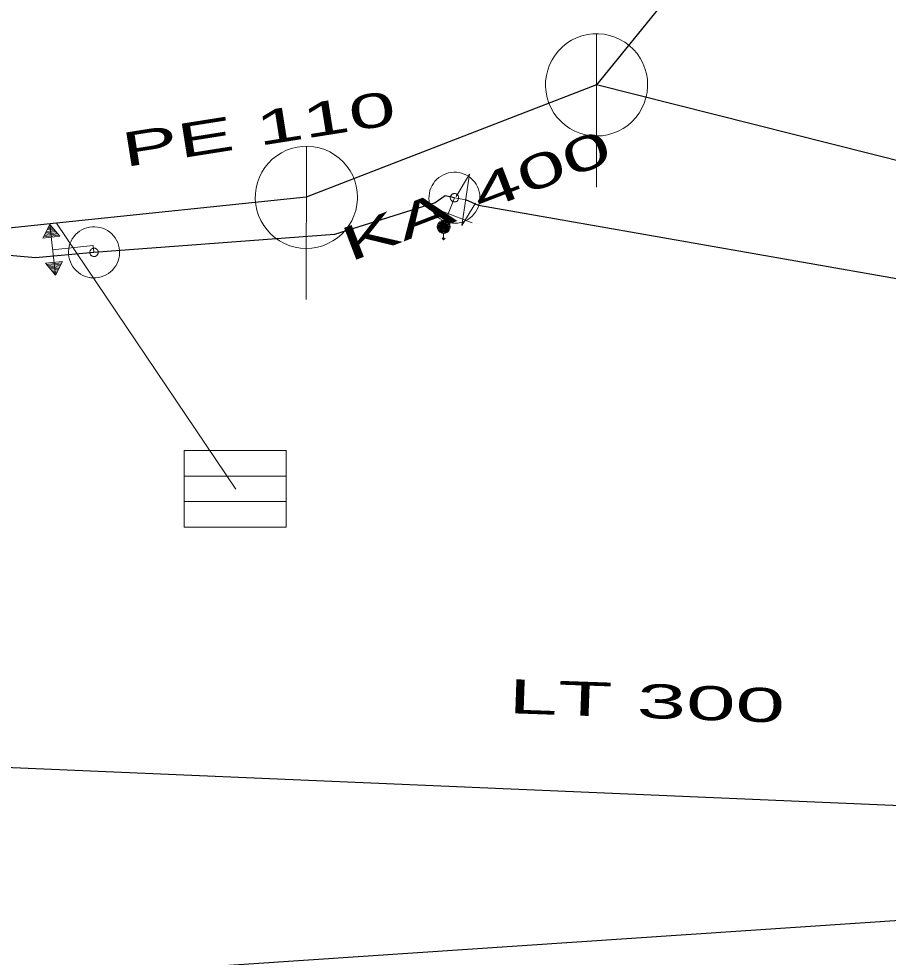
# Model space of a CAD drawing. Extents: x -687593 to -687108, y -975254 to -974717.
# Drawn here: x -687489.87 to -687472.85, y -974906.1 to -974887.74 of the extents above; entities that cross this region are included whole.
import ezdxf
from ezdxf.enums import TextEntityAlignment as Align

# ---------------------------------------------------------------- set-up
doc = ezdxf.new("R2010")
doc.units = 0
doc.header["$LTSCALE"] = 0.27
for name, color, linetype, lineweight in [('1', 7, 'Continuous', 25), ('11', 7, 'Continuous', 13), ('14', 7, 'Continuous', 13), ('17', 7, 'Continuous', 25), ('22', 7, 'Continuous', 13), ('34', 7, 'Continuous', 13), ('47', 7, 'Continuous', 13), ('9', 7, 'Continuous', 13)]:
    doc.layers.add(name, color=color, linetype=linetype, lineweight=lineweight)

msp = doc.modelspace()

# ---------------------------------------------------------------- linework, layer by layer
at = {"layer": '1'}
msp.add_lwpolyline([(-687190.553, -975166.941), (-687164.86, -975177.861), (-687155.924, -975158.837), (-687125.348, -975155.541), (-687124.826, -975139.621), (-687173.065, -975131.89), (-687231.828, -975028.025), (-687222.959, -975015.464), (-687237.898, -975004.026), (-687247.4, -975009.654), (-687276.892, -974983.781), (-687453.606, -974886.044), (-687460.232, -974860.45), (-687474.874, -974858.564), (-687482.889, -974882.272), (-687502.421, -974882.802), (-687499.452, -974907.164), (-687464.42, -974904.824), (-687331.319, -974973.728), (-687252.566, -975037.916), (-687192.379, -975151.48)], close=True, dxfattribs=at)
at = {"layer": '11'}
msp.add_line((-687485.62, -974896.94), (-687489.129, -974891.737), dxfattribs=at)
at = {"layer": '14', "lineweight": 25}
for p, q in [((-687462.829, -974869.623), (-687478.559, -974889.03)), ((-687478.559, -974889.03), (-687484.239, -974891.23)), ((-687459.21, -974893.91), (-687478.559, -974889.03))]:
    msp.add_line(p, q, dxfattribs=at)
at = {"layer": '14'}
for p, q in [((-687481.34, -974891.239), (-687481.46, -974891.55)), ((-687481.12, -974891.28), (-687481.34, -974891.239)), ((-687481.46, -974891.55), (-687481.55, -974891.809)), ((-687488.395, -974892.307), (-687488.41, -974892.17))]:
    msp.add_line(p, q, dxfattribs=at)
at = {"layer": '14', "lineweight": 25}
msp.add_lwpolyline([(-687484.239, -974891.23), (-687489.129, -974891.737), (-687501.93, -974893.079)], dxfattribs=at)
at = {"layer": '17'}
for points in [[(-687481.34, -974891.239), (-687481.52, -974891.199), (-687481.719, -974891.34), (-687483.69, -974891.96), (-687488.395, -974892.307)], [(-687440.137, -974904.525), (-687461.23, -974894.833), (-687480.87, -974891.39), (-687481.12, -974891.28)], [(-687488.395, -974892.307), (-687489.541, -974892.416), (-687490.936, -974892.292), (-687501.809, -974893.949), (-687502.346, -974893.334), (-687503.5, -974891.899)], [(-687397.965, -974929.018), (-687440.137, -974904.525), (-687515.147, -974901.318)]]:
    msp.add_lwpolyline(points, dxfattribs=at)
at = {"layer": '22'}
for p, q in [((-687478.559, -974891.03), (-687478.558, -974888.03)), ((-687484.239, -974893.23), (-687484.238, -974890.23)), ((-687486.631, -974896.683), (-687484.631, -974896.683)), ((-687486.631, -974897.183), (-687484.631, -974897.183))]:
    msp.add_line(p, q, dxfattribs=at)
for points in [[(-687477.559, -974889.03), (-687477.564, -974888.921), (-687477.582, -974888.813), (-687477.612, -974888.707), (-687477.652, -974888.606), (-687477.704, -974888.509), (-687477.766, -974888.419), (-687477.838, -974888.336), (-687477.918, -974888.262), (-687478.006, -974888.196), (-687478.1, -974888.141), (-687478.2, -974888.096), (-687478.305, -974888.063), (-687478.412, -974888.041), (-687478.521, -974888.031), (-687478.631, -974888.033), (-687478.739, -974888.047), (-687478.846, -974888.072), (-687478.949, -974888.109), (-687479.047, -974888.158), (-687479.139, -974888.216), (-687479.225, -974888.285), (-687479.302, -974888.362), (-687479.371, -974888.448), (-687479.43, -974888.54), (-687479.478, -974888.638), (-687479.515, -974888.741), (-687479.541, -974888.848), (-687479.555, -974888.956), (-687479.558, -974889.066), (-687479.548, -974889.175), (-687479.527, -974889.282), (-687479.493, -974889.386), (-687479.449, -974889.486), (-687479.394, -974889.581), (-687479.328, -974889.669), (-687479.254, -974889.749), (-687479.171, -974889.821), (-687479.081, -974889.883), (-687478.985, -974889.935), (-687478.883, -974889.976), (-687478.778, -974890.006), (-687478.67, -974890.024), (-687478.56, -974890.03), (-687478.451, -974890.024), (-687478.343, -974890.006), (-687478.238, -974889.977), (-687478.136, -974889.936), (-687478.039, -974889.884), (-687477.949, -974889.822), (-687477.866, -974889.751), (-687477.791, -974889.671), (-687477.726, -974889.583), (-687477.67, -974889.489), (-687477.626, -974889.389), (-687477.592, -974889.285), (-687477.57, -974889.177), (-687477.56, -974889.068)], [(-687483.239, -974891.23), (-687483.244, -974891.121), (-687483.262, -974891.013), (-687483.292, -974890.907), (-687483.332, -974890.806), (-687483.384, -974890.709), (-687483.446, -974890.619), (-687483.518, -974890.536), (-687483.598, -974890.462), (-687483.686, -974890.396), (-687483.78, -974890.341), (-687483.88, -974890.296), (-687483.985, -974890.263), (-687484.092, -974890.241), (-687484.201, -974890.231), (-687484.311, -974890.233), (-687484.419, -974890.247), (-687484.526, -974890.272), (-687484.629, -974890.309), (-687484.727, -974890.358), (-687484.819, -974890.416), (-687484.905, -974890.485), (-687484.982, -974890.562), (-687485.051, -974890.648), (-687485.11, -974890.74), (-687485.158, -974890.838), (-687485.195, -974890.941), (-687485.221, -974891.048), (-687485.235, -974891.156), (-687485.238, -974891.266), (-687485.228, -974891.375), (-687485.207, -974891.482), (-687485.173, -974891.586), (-687485.129, -974891.686), (-687485.074, -974891.781), (-687485.008, -974891.869), (-687484.934, -974891.949), (-687484.851, -974892.021), (-687484.761, -974892.083), (-687484.665, -974892.135), (-687484.563, -974892.176), (-687484.458, -974892.206), (-687484.35, -974892.224), (-687484.24, -974892.23), (-687484.131, -974892.224), (-687484.023, -974892.206), (-687483.918, -974892.177), (-687483.816, -974892.136), (-687483.719, -974892.084), (-687483.629, -974892.022), (-687483.546, -974891.951), (-687483.471, -974891.871), (-687483.406, -974891.783), (-687483.35, -974891.689), (-687483.306, -974891.589), (-687483.272, -974891.485), (-687483.25, -974891.377), (-687483.24, -974891.268)], [(-687486.631, -974896.183), (-687484.631, -974896.183), (-687484.631, -974897.683), (-687486.631, -974897.683)]]:
    msp.add_lwpolyline(points, close=True, dxfattribs=at)
at = {"layer": '34'}
for p, q in [((-687480.993, -974891.73), (-687481.926, -974891.369)), ((-687489.369, -974891.976), (-687489.103, -974891.944)), ((-687489.352, -974891.95), (-687489.125, -974891.922)), ((-687489.339, -974891.923), (-687489.144, -974891.9)), ((-687489.326, -974891.899), (-687489.161, -974891.879)), ((-687489.314, -974891.869), (-687489.181, -974891.854)), ((-687489.301, -974891.845), (-687489.199, -974891.832)), ((-687489.284, -974891.819), (-687489.222, -974891.811)), ((-687489.273, -974891.788), (-687489.241, -974891.785)), ((-687489.381, -974892.004), (-687489.084, -974891.969)), ((-687489.205, -974892.257), (-687488.41, -974892.17)), ((-687489.011, -974892.487), (-687489.151, -974892.75)), ((-687489.322, -974892.541), (-687489.024, -974892.511)), ((-687489.304, -974892.566), (-687489.037, -974892.54)), ((-687489.282, -974892.588), (-687489.055, -974892.566)), ((-687489.264, -974892.611), (-687489.068, -974892.592)), ((-687489.246, -974892.632), (-687489.08, -974892.616)), ((-687489.228, -974892.658), (-687489.094, -974892.645)), ((-687489.209, -974892.68), (-687489.108, -974892.669)), ((-687489.188, -974892.701), (-687489.125, -974892.695)), ((-687489.17, -974892.729), (-687489.138, -974892.725))]:
    msp.add_line(p, q, dxfattribs=at)
for points in [[(-687489.259, -974891.764), (-687489.394, -974892.03), (-687489.065, -974891.99)], [(-687489.065, -974891.99), (-687489.259, -974891.764), (-687489.151, -974892.75)], [(-687489.151, -974892.75), (-687489.341, -974892.519), (-687489.011, -974892.487)]]:
    msp.add_lwpolyline(points, dxfattribs=at)
at = {"layer": '47'}
msp.add_line((-687481.193, -974891.784), (-687480.93, -974891.346), dxfattribs=at)
for points in [[(-687481.831, -974891.149), (-687481.838, -974891.201), (-687481.839, -974891.253), (-687481.834, -974891.305), (-687481.825, -974891.356), (-687481.81, -974891.407), (-687481.79, -974891.455), (-687481.764, -974891.501), (-687481.734, -974891.544), (-687481.701, -974891.583), (-687481.663, -974891.62), (-687481.621, -974891.652), (-687481.576, -974891.678), (-687481.529, -974891.701), (-687481.48, -974891.718), (-687481.429, -974891.73), (-687481.377, -974891.737), (-687481.325, -974891.738), (-687481.272, -974891.734), (-687481.222, -974891.724), (-687481.171, -974891.709), (-687481.123, -974891.689), (-687481.076, -974891.663), (-687481.033, -974891.634), (-687480.994, -974891.6), (-687480.958, -974891.562), (-687480.926, -974891.52), (-687480.899, -974891.475), (-687480.877, -974891.428), (-687480.86, -974891.379), (-687480.848, -974891.328), (-687480.841, -974891.276), (-687480.84, -974891.224), (-687480.843, -974891.171), (-687480.854, -974891.121), (-687480.869, -974891.07), (-687480.888, -974891.022), (-687480.914, -974890.975), (-687480.943, -974890.932), (-687480.978, -974890.893), (-687481.016, -974890.857), (-687481.058, -974890.825), (-687481.102, -974890.798), (-687481.15, -974890.776), (-687481.199, -974890.759), (-687481.25, -974890.747), (-687481.302, -974890.74), (-687481.354, -974890.739), (-687481.406, -974890.743), (-687481.457, -974890.753), (-687481.508, -974890.768), (-687481.556, -974890.787), (-687481.602, -974890.813), (-687481.645, -974890.843), (-687481.684, -974890.877), (-687481.721, -974890.915), (-687481.753, -974890.957), (-687481.779, -974891.001), (-687481.802, -974891.049), (-687481.819, -974891.098)], [(-687481.42, -974891.224), (-687481.422, -974891.233), (-687481.421, -974891.241), (-687481.421, -974891.249), (-687481.419, -974891.258), (-687481.417, -974891.266), (-687481.413, -974891.274), (-687481.409, -974891.282), (-687481.405, -974891.289), (-687481.399, -974891.295), (-687481.393, -974891.301), (-687481.385, -974891.306), (-687481.378, -974891.311), (-687481.371, -974891.314), (-687481.363, -974891.318), (-687481.354, -974891.319), (-687481.345, -974891.321), (-687481.337, -974891.32), (-687481.329, -974891.32), (-687481.32, -974891.318), (-687481.312, -974891.316), (-687481.304, -974891.312), (-687481.296, -974891.308), (-687481.289, -974891.304), (-687481.282, -974891.298), (-687481.277, -974891.292), (-687481.272, -974891.284), (-687481.267, -974891.277), (-687481.264, -974891.27), (-687481.26, -974891.262), (-687481.259, -974891.253), (-687481.257, -974891.244), (-687481.258, -974891.236), (-687481.258, -974891.228), (-687481.26, -974891.219), (-687481.262, -974891.211), (-687481.265, -974891.203), (-687481.27, -974891.195), (-687481.274, -974891.188), (-687481.28, -974891.181), (-687481.286, -974891.176), (-687481.294, -974891.171), (-687481.301, -974891.166), (-687481.308, -974891.163), (-687481.316, -974891.159), (-687481.325, -974891.158), (-687481.334, -974891.156), (-687481.342, -974891.157), (-687481.35, -974891.157), (-687481.359, -974891.159), (-687481.367, -974891.161), (-687481.375, -974891.164), (-687481.383, -974891.169), (-687481.39, -974891.173), (-687481.396, -974891.179), (-687481.402, -974891.185), (-687481.407, -974891.193), (-687481.412, -974891.2), (-687481.415, -974891.207), (-687481.419, -974891.215)], [(-687488.893, -974892.343), (-687488.886, -974892.395), (-687488.875, -974892.446), (-687488.857, -974892.495), (-687488.835, -974892.543), (-687488.808, -974892.588), (-687488.776, -974892.629), (-687488.74, -974892.667), (-687488.7, -974892.701), (-687488.658, -974892.731), (-687488.612, -974892.757), (-687488.563, -974892.777), (-687488.513, -974892.792), (-687488.462, -974892.802), (-687488.41, -974892.806), (-687488.358, -974892.805), (-687488.306, -974892.798), (-687488.255, -974892.787), (-687488.205, -974892.769), (-687488.158, -974892.747), (-687488.113, -974892.72), (-687488.072, -974892.688), (-687488.033, -974892.652), (-687487.999, -974892.612), (-687487.969, -974892.57), (-687487.944, -974892.524), (-687487.924, -974892.475), (-687487.908, -974892.425), (-687487.899, -974892.374), (-687487.895, -974892.322), (-687487.896, -974892.27), (-687487.903, -974892.218), (-687487.914, -974892.167), (-687487.931, -974892.117), (-687487.954, -974892.07), (-687487.981, -974892.025), (-687488.012, -974891.984), (-687488.048, -974891.945), (-687488.088, -974891.911), (-687488.131, -974891.881), (-687488.177, -974891.856), (-687488.226, -974891.836), (-687488.275, -974891.82), (-687488.327, -974891.811), (-687488.379, -974891.807), (-687488.431, -974891.808), (-687488.483, -974891.815), (-687488.534, -974891.826), (-687488.583, -974891.843), (-687488.631, -974891.866), (-687488.676, -974891.893), (-687488.717, -974891.924), (-687488.755, -974891.96), (-687488.789, -974892), (-687488.819, -974892.043), (-687488.845, -974892.089), (-687488.865, -974892.138), (-687488.88, -974892.187), (-687488.89, -974892.239), (-687488.894, -974892.291)], [(-687488.476, -974892.313), (-687488.476, -974892.322), (-687488.473, -974892.329), (-687488.47, -974892.337), (-687488.467, -974892.345), (-687488.462, -974892.353), (-687488.457, -974892.359), (-687488.451, -974892.366), (-687488.445, -974892.371), (-687488.438, -974892.376), (-687488.43, -974892.38), (-687488.422, -974892.384), (-687488.414, -974892.386), (-687488.406, -974892.388), (-687488.397, -974892.389), (-687488.388, -974892.388), (-687488.379, -974892.388), (-687488.372, -974892.385), (-687488.364, -974892.382), (-687488.356, -974892.379), (-687488.348, -974892.374), (-687488.342, -974892.369), (-687488.335, -974892.363), (-687488.33, -974892.357), (-687488.324, -974892.349), (-687488.321, -974892.342), (-687488.317, -974892.334), (-687488.315, -974892.326), (-687488.313, -974892.318), (-687488.312, -974892.309), (-687488.313, -974892.3), (-687488.313, -974892.291), (-687488.316, -974892.284), (-687488.319, -974892.276), (-687488.322, -974892.268), (-687488.327, -974892.26), (-687488.331, -974892.254), (-687488.338, -974892.247), (-687488.344, -974892.242), (-687488.352, -974892.236), (-687488.359, -974892.233), (-687488.367, -974892.229), (-687488.375, -974892.227), (-687488.383, -974892.225), (-687488.392, -974892.224), (-687488.401, -974892.225), (-687488.41, -974892.225), (-687488.417, -974892.228), (-687488.425, -974892.231), (-687488.433, -974892.234), (-687488.441, -974892.239), (-687488.447, -974892.243), (-687488.454, -974892.25), (-687488.459, -974892.256), (-687488.464, -974892.263), (-687488.468, -974892.271), (-687488.472, -974892.279), (-687488.474, -974892.287), (-687488.476, -974892.295), (-687488.477, -974892.304)]]:
    msp.add_lwpolyline(points, close=True, dxfattribs=at)
msp.add_lwpolyline([(-687481.193, -974891.784), (-687481.046, -974890.775), (-687481.309, -974891.213)], dxfattribs=at)
at = {"layer": '9'}
msp.add_line((-687481.551, -974891.936), (-687481.551, -974892.061), dxfattribs=at)
for points in [[(-687481.677, -974891.808), (-687481.676, -974891.821), (-687481.674, -974891.834), (-687481.671, -974891.847), (-687481.666, -974891.859), (-687481.66, -974891.871), (-687481.653, -974891.882), (-687481.645, -974891.892), (-687481.635, -974891.902), (-687481.625, -974891.91), (-687481.614, -974891.917), (-687481.602, -974891.923), (-687481.59, -974891.928), (-687481.577, -974891.931), (-687481.564, -974891.933), (-687481.551, -974891.936), (-687481.538, -974891.935), (-687481.525, -974891.933), (-687481.512, -974891.93), (-687481.5, -974891.925), (-687481.488, -974891.919), (-687481.477, -974891.912), (-687481.467, -974891.904), (-687481.457, -974891.894), (-687481.449, -974891.884), (-687481.442, -974891.873), (-687481.436, -974891.861), (-687481.431, -974891.849), (-687481.428, -974891.836), (-687481.426, -974891.823), (-687481.424, -974891.81), (-687481.425, -974891.797), (-687481.427, -974891.784), (-687481.43, -974891.771), (-687481.435, -974891.759), (-687481.441, -974891.747), (-687481.448, -974891.736), (-687481.456, -974891.726), (-687481.466, -974891.716), (-687481.476, -974891.708), (-687481.487, -974891.701), (-687481.499, -974891.695), (-687481.511, -974891.69), (-687481.524, -974891.687), (-687481.537, -974891.685), (-687481.55, -974891.683), (-687481.563, -974891.683), (-687481.576, -974891.685), (-687481.589, -974891.688), (-687481.601, -974891.693), (-687481.613, -974891.699), (-687481.624, -974891.706), (-687481.634, -974891.714), (-687481.644, -974891.724), (-687481.652, -974891.734), (-687481.659, -974891.745), (-687481.665, -974891.757), (-687481.67, -974891.769), (-687481.673, -974891.782), (-687481.675, -974891.795)], [(-687481.657, -974891.808), (-687481.657, -974891.819), (-687481.655, -974891.83), (-687481.652, -974891.841), (-687481.648, -974891.851), (-687481.643, -974891.861), (-687481.637, -974891.87), (-687481.63, -974891.879), (-687481.622, -974891.887), (-687481.613, -974891.894), (-687481.604, -974891.9), (-687481.594, -974891.905), (-687481.584, -974891.909), (-687481.573, -974891.912), (-687481.562, -974891.914), (-687481.551, -974891.914), (-687481.54, -974891.916), (-687481.529, -974891.914), (-687481.518, -974891.911), (-687481.508, -974891.907), (-687481.498, -974891.902), (-687481.489, -974891.896), (-687481.48, -974891.889), (-687481.472, -974891.881), (-687481.465, -974891.872), (-687481.459, -974891.863), (-687481.454, -974891.853), (-687481.45, -974891.843), (-687481.447, -974891.832), (-687481.445, -974891.821), (-687481.444, -974891.81), (-687481.444, -974891.799), (-687481.446, -974891.788), (-687481.449, -974891.777), (-687481.453, -974891.767), (-687481.458, -974891.757), (-687481.464, -974891.748), (-687481.471, -974891.739), (-687481.479, -974891.731), (-687481.488, -974891.724), (-687481.497, -974891.718), (-687481.507, -974891.713), (-687481.517, -974891.709), (-687481.528, -974891.706), (-687481.539, -974891.704), (-687481.55, -974891.703), (-687481.561, -974891.702), (-687481.572, -974891.704), (-687481.583, -974891.707), (-687481.593, -974891.711), (-687481.603, -974891.716), (-687481.612, -974891.722), (-687481.621, -974891.729), (-687481.629, -974891.737), (-687481.636, -974891.746), (-687481.642, -974891.755), (-687481.647, -974891.765), (-687481.651, -974891.775), (-687481.654, -974891.786), (-687481.656, -974891.797)], [(-687481.638, -974891.808), (-687481.637, -974891.817), (-687481.636, -974891.826), (-687481.633, -974891.835), (-687481.63, -974891.843), (-687481.626, -974891.851), (-687481.621, -974891.859), (-687481.615, -974891.866), (-687481.609, -974891.872), (-687481.602, -974891.878), (-687481.594, -974891.883), (-687481.586, -974891.887), (-687481.578, -974891.89), (-687481.569, -974891.893), (-687481.56, -974891.894), (-687481.551, -974891.897), (-687481.542, -974891.896), (-687481.533, -974891.895), (-687481.524, -974891.892), (-687481.516, -974891.889), (-687481.508, -974891.885), (-687481.5, -974891.88), (-687481.493, -974891.874), (-687481.487, -974891.868), (-687481.481, -974891.861), (-687481.476, -974891.853), (-687481.472, -974891.845), (-687481.469, -974891.837), (-687481.466, -974891.828), (-687481.465, -974891.819), (-687481.463, -974891.81), (-687481.464, -974891.801), (-687481.465, -974891.792), (-687481.468, -974891.783), (-687481.471, -974891.775), (-687481.475, -974891.767), (-687481.48, -974891.759), (-687481.486, -974891.752), (-687481.492, -974891.746), (-687481.499, -974891.74), (-687481.507, -974891.735), (-687481.515, -974891.731), (-687481.523, -974891.728), (-687481.532, -974891.725), (-687481.541, -974891.724), (-687481.55, -974891.722), (-687481.559, -974891.722), (-687481.568, -974891.723), (-687481.577, -974891.726), (-687481.585, -974891.729), (-687481.593, -974891.733), (-687481.601, -974891.738), (-687481.608, -974891.744), (-687481.614, -974891.75), (-687481.62, -974891.757), (-687481.625, -974891.765), (-687481.629, -974891.773), (-687481.632, -974891.781), (-687481.635, -974891.79), (-687481.636, -974891.799)], [(-687481.618, -974891.808), (-687481.618, -974891.815), (-687481.616, -974891.822), (-687481.615, -974891.829), (-687481.612, -974891.835), (-687481.609, -974891.841), (-687481.605, -974891.847), (-687481.601, -974891.853), (-687481.596, -974891.858), (-687481.59, -974891.862), (-687481.584, -974891.866), (-687481.578, -974891.869), (-687481.572, -974891.872), (-687481.565, -974891.873), (-687481.558, -974891.875), (-687481.551, -974891.875), (-687481.544, -974891.877), (-687481.537, -974891.875), (-687481.53, -974891.874), (-687481.524, -974891.871), (-687481.517, -974891.868), (-687481.512, -974891.864), (-687481.506, -974891.86), (-687481.501, -974891.855), (-687481.497, -974891.849), (-687481.493, -974891.843), (-687481.49, -974891.837), (-687481.487, -974891.831), (-687481.485, -974891.824), (-687481.484, -974891.817), (-687481.483, -974891.81), (-687481.483, -974891.803), (-687481.484, -974891.796), (-687481.486, -974891.789), (-687481.489, -974891.783), (-687481.492, -974891.776), (-687481.496, -974891.771), (-687481.5, -974891.765), (-687481.505, -974891.76), (-687481.511, -974891.756), (-687481.516, -974891.752), (-687481.523, -974891.749), (-687481.529, -974891.746), (-687481.536, -974891.744), (-687481.543, -974891.743), (-687481.55, -974891.742), (-687481.557, -974891.741), (-687481.564, -974891.742), (-687481.571, -974891.744), (-687481.577, -974891.747), (-687481.583, -974891.75), (-687481.589, -974891.754), (-687481.595, -974891.758), (-687481.6, -974891.763), (-687481.604, -974891.769), (-687481.608, -974891.774), (-687481.611, -974891.781), (-687481.614, -974891.787), (-687481.615, -974891.794), (-687481.617, -974891.801)], [(-687481.598, -974891.808), (-687481.598, -974891.813), (-687481.597, -974891.818), (-687481.596, -974891.823), (-687481.594, -974891.827), (-687481.592, -974891.832), (-687481.589, -974891.836), (-687481.586, -974891.839), (-687481.582, -974891.843), (-687481.579, -974891.846), (-687481.575, -974891.849), (-687481.57, -974891.851), (-687481.566, -974891.853), (-687481.561, -974891.854), (-687481.556, -974891.855), (-687481.551, -974891.855), (-687481.546, -974891.857), (-687481.541, -974891.856), (-687481.536, -974891.855), (-687481.532, -974891.853), (-687481.527, -974891.851), (-687481.523, -974891.848), (-687481.519, -974891.845), (-687481.516, -974891.841), (-687481.513, -974891.838), (-687481.51, -974891.834), (-687481.508, -974891.829), (-687481.506, -974891.825), (-687481.505, -974891.82), (-687481.504, -974891.815), (-687481.504, -974891.81), (-687481.503, -974891.805), (-687481.504, -974891.8), (-687481.505, -974891.795), (-687481.507, -974891.791), (-687481.509, -974891.786), (-687481.512, -974891.782), (-687481.515, -974891.778), (-687481.518, -974891.775), (-687481.522, -974891.772), (-687481.526, -974891.769), (-687481.531, -974891.767), (-687481.535, -974891.765), (-687481.54, -974891.764), (-687481.545, -974891.763), (-687481.55, -974891.762), (-687481.555, -974891.761), (-687481.56, -974891.762), (-687481.565, -974891.763), (-687481.569, -974891.765), (-687481.574, -974891.767), (-687481.578, -974891.77), (-687481.581, -974891.773), (-687481.585, -974891.776), (-687481.588, -974891.78), (-687481.591, -974891.784), (-687481.593, -974891.789), (-687481.595, -974891.793), (-687481.596, -974891.798), (-687481.597, -974891.803)], [(-687481.578, -974891.808), (-687481.578, -974891.811), (-687481.578, -974891.814), (-687481.577, -974891.816), (-687481.576, -974891.819), (-687481.575, -974891.822), (-687481.573, -974891.824), (-687481.571, -974891.826), (-687481.569, -974891.828), (-687481.567, -974891.83), (-687481.565, -974891.832), (-687481.562, -974891.833), (-687481.559, -974891.834), (-687481.557, -974891.835), (-687481.554, -974891.835), (-687481.551, -974891.835), (-687481.548, -974891.837), (-687481.545, -974891.837), (-687481.542, -974891.836), (-687481.54, -974891.835), (-687481.537, -974891.834), (-687481.535, -974891.832), (-687481.532, -974891.83), (-687481.53, -974891.828), (-687481.529, -974891.826), (-687481.527, -974891.824), (-687481.526, -974891.821), (-687481.525, -974891.818), (-687481.524, -974891.816), (-687481.524, -974891.813), (-687481.522, -974891.81), (-687481.523, -974891.807), (-687481.523, -974891.804), (-687481.524, -974891.801), (-687481.525, -974891.799), (-687481.526, -974891.796), (-687481.528, -974891.794), (-687481.529, -974891.791), (-687481.531, -974891.789), (-687481.534, -974891.788), (-687481.536, -974891.786), (-687481.539, -974891.785), (-687481.541, -974891.784), (-687481.544, -974891.783), (-687481.547, -974891.783), (-687481.55, -974891.781), (-687481.553, -974891.781), (-687481.556, -974891.781), (-687481.558, -974891.782), (-687481.561, -974891.783), (-687481.564, -974891.784), (-687481.566, -974891.786), (-687481.568, -974891.787), (-687481.57, -974891.789), (-687481.572, -974891.792), (-687481.574, -974891.794), (-687481.575, -974891.797), (-687481.576, -974891.799), (-687481.577, -974891.802), (-687481.577, -974891.805)], [(-687481.559, -974891.808), (-687481.559, -974891.809), (-687481.559, -974891.81), (-687481.558, -974891.81), (-687481.558, -974891.811), (-687481.558, -974891.812), (-687481.557, -974891.813), (-687481.557, -974891.813), (-687481.556, -974891.814), (-687481.556, -974891.814), (-687481.555, -974891.815), (-687481.554, -974891.815), (-687481.553, -974891.815), (-687481.553, -974891.816), (-687481.552, -974891.816), (-687481.551, -974891.816), (-687481.55, -974891.817), (-687481.549, -974891.817), (-687481.549, -974891.817), (-687481.548, -974891.817), (-687481.547, -974891.817), (-687481.546, -974891.816), (-687481.546, -974891.816), (-687481.545, -974891.815), (-687481.545, -974891.815), (-687481.544, -974891.814), (-687481.544, -974891.813), (-687481.543, -974891.812), (-687481.543, -974891.812), (-687481.543, -974891.811), (-687481.542, -974891.81), (-687481.542, -974891.809), (-687481.542, -974891.808), (-687481.542, -974891.808), (-687481.543, -974891.807), (-687481.543, -974891.806), (-687481.544, -974891.805), (-687481.544, -974891.805), (-687481.545, -974891.804), (-687481.545, -974891.804), (-687481.546, -974891.803), (-687481.547, -974891.803), (-687481.548, -974891.802), (-687481.548, -974891.802), (-687481.549, -974891.802), (-687481.55, -974891.801), (-687481.551, -974891.801), (-687481.552, -974891.8), (-687481.552, -974891.8), (-687481.553, -974891.801), (-687481.554, -974891.801), (-687481.555, -974891.802), (-687481.555, -974891.802), (-687481.556, -974891.803), (-687481.556, -974891.803), (-687481.557, -974891.804), (-687481.557, -974891.805), (-687481.557, -974891.806), (-687481.558, -974891.806), (-687481.558, -974891.807)]]:
    msp.add_lwpolyline(points, close=True, dxfattribs=at)
msp.add_lwpolyline([(-687481.52, -974892.027), (-687481.551, -974892.061), (-687481.582, -974892.025)], dxfattribs=at)

# ---------------------------------------------------------------- texts
at = {"layer": '1'}
for s, rotation, width, p in [('PE 110', 9, 1.85, (-687485.1201, -974890.217)), ('PE 110', 9, 1.85, (-687485.1201, -974890.217)), ('PE 110', 9, 1.85, (-687485.1201, -974890.217)), ('PE 110', 9, 1.85, (-687485.1201, -974890.217)), ('PE 110', 9, 1.85, (-687485.1201, -974890.217)), ('KA 400', 21, 1.9, (-687480.7965, -974891.5043)), ('KA 400', 21, 1.9, (-687480.7965, -974891.5043)), ('KA 400', 21, 1.9, (-687480.7965, -974891.5043)), ('KA 400', 21, 1.9, (-687480.7965, -974891.5043)), ('KA 400', 21, 1.9, (-687480.7965, -974891.5043)), ('LT 300', 358, 1.95, (-687477.5876, -974901.4153)), ('LT 300', 358, 1.95, (-687477.5876, -974901.4153)), ('LT 300', 358, 1.95, (-687477.5876, -974901.4153)), ('LT 300', 358, 1.95, (-687477.5876, -974901.4153)), ('LT 300', 358, 1.95, (-687477.5876, -974901.4153))]:
    msp.add_text(s, height=0.6667, rotation=rotation, dxfattribs=dict(at, width=width)).set_placement(p, align=Align.CENTER)

doc.saveas('drawing.dxf')
